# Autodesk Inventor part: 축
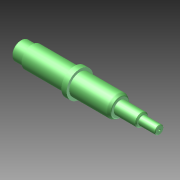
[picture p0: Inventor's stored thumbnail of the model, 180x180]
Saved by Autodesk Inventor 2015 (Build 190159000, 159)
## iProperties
Created: 2024-12
Part Number: 축
Material: 일반
Document SubType Name: Modeling
Designer: 10401
Density: 1 g/cm^3
Appearance: 기본값
Author: 10401
Author: jhkim
Creation Date: 2024-11-28
Sending System: Autodesk Inventor 2025
Preprocessor: ST-DEVELOPER v20
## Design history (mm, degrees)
node "축1"
node "솔리드1"
node "기준1"
